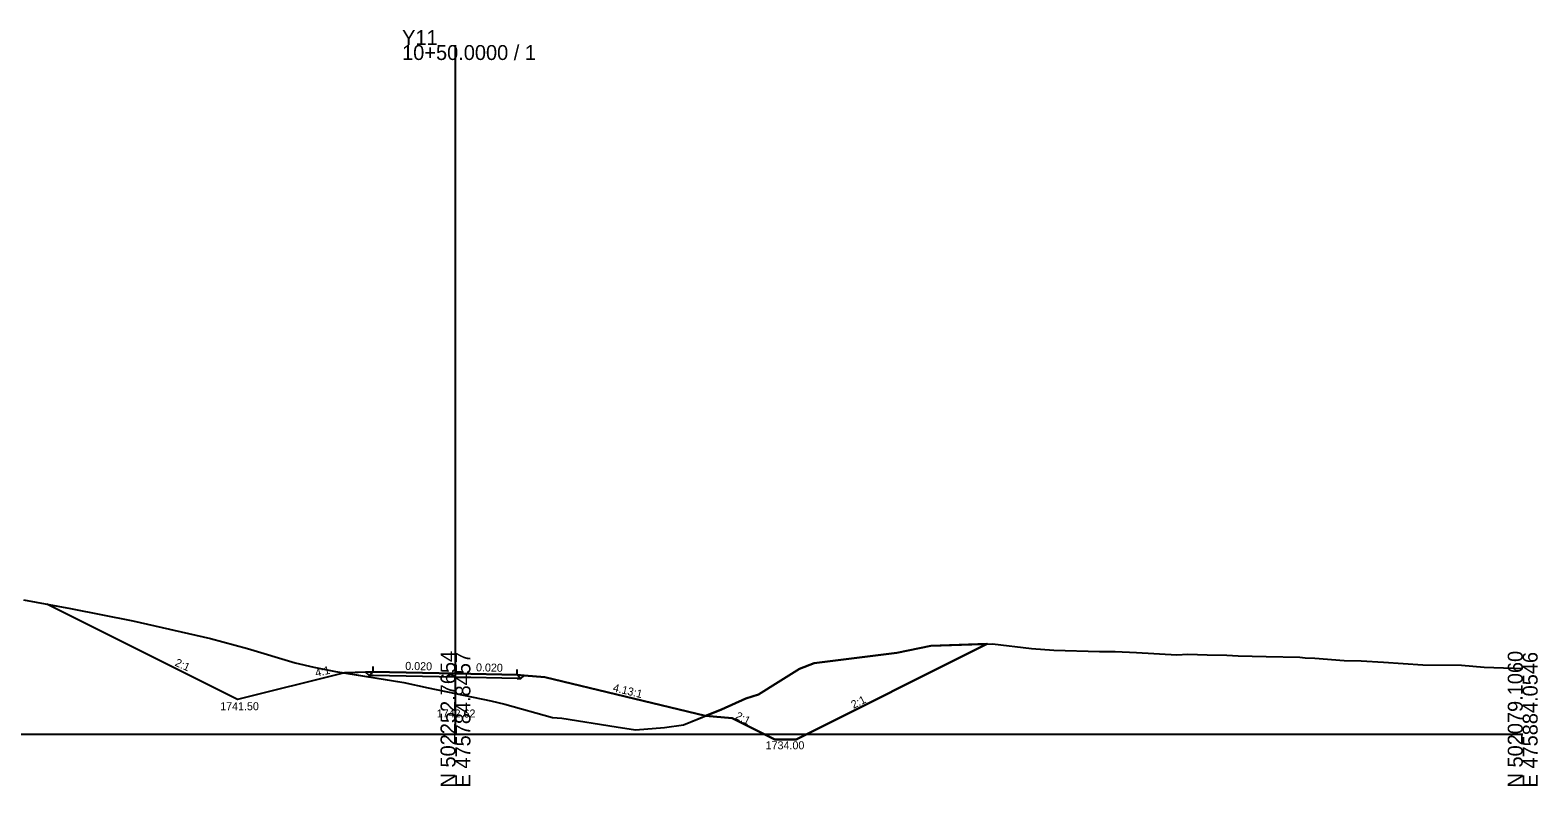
# Model space of a CAD drawing. Extents: x -76 to 353, y -10 to 8186.
# Drawn here: x 70.3 to 352.8, y 990.3 to 1132 of the extents above; entities that cross this region are included whole.
import ezdxf

# ---------------------------------------------------------------- set-up
doc = ezdxf.new("R2010")
doc.units = 0
for name, color, linetype in [('Exist Cross Section Cell', 7, 'Continuous'), ('Exist XS Center Line Elevation Label', 7, 'Continuous'), ('Exist XS Ground Line', 7, 'Continuous'), ('Prop XS DDE', 7, 'Continuous'), ('Prop XS DDE Earthwork Shape', 7, 'Continuous'), ('Prop XS Ditch Slope Text', 7, 'Continuous'), ('Prop XS Ditch Standard Text', 7, 'Continuous'), ('Prop XS Dump Level', 7, 'Continuous'), ('Prop XS Earthwork Shape', 7, 'Continuous'), ('Prop XS EOT Tick Mark', 7, 'Continuous'), ('Prop XS Finish Grade', 7, 'Continuous'), ('Prop XS Finish Grade Earthwork', 7, 'Continuous'), ('Prop XS Finish Grade Pavement', 7, 'Continuous'), ('Prop XS Hydro Fill Slope Data', 7, 'Continuous'), ('Prop XS Hydro Typical Ditch Data', 7, 'Continuous'), ('Prop XS Pvmt Edge Slope', 7, 'Continuous'), ('Prop XS SE Text', 7, 'Continuous'), ('Prop XS Shoulder Borrow Shape', 7, 'Continuous'), ('Prop XS Side Slope Text', 7, 'Continuous'), ('Prop XS Subgrade Earthwork', 7, 'Continuous'), ('Scratch_Level_3', 7, 'Continuous')]:
    doc.layers.add(name, color=color, linetype=linetype)

msp = doc.modelspace()

# ---------------------------------------------------------------- linework, layer by layer
at = {"layer": 'Exist Cross Section Cell'}
for p, q in [((150, 1000), (150, 1129.16)), ((-50, 1000), (150, 1000)), ((150, 1000), (350, 1000))]:
    msp.add_line(p, q, dxfattribs=at)
at = {"layer": 'Exist XS Ground Line'}
msp.add_lwpolyline([(69.06, 1025.17), (77.84, 1023.54), (89.53, 1021.21), (104.1, 1017.94), (111.04, 1016.05), (119.93, 1013.39), (123.43, 1012.56), (127.52, 1011.74), (140.3, 1009.65), (144.88, 1008.69), (150, 1007.62), (156.63, 1006.23), (159.24, 1005.62), (168.21, 1003.15), (169.96, 1002.97), (180.14, 1001.4), (183.72, 1000.78), (189.17, 1001.22), (192.71, 1001.75), (199.86, 1004.61), (204.39, 1006.7), (206.81, 1007.44), (210.45, 1009.73), (214.49, 1012.24), (217.21, 1013.3), (232.73, 1015.23), (239.1, 1016.54), (250.62, 1016.94), (257.92, 1016.05), (262.14, 1015.77), (270.7, 1015.51), (273.66, 1015.46), (277.61, 1015.3), (285.18, 1014.89), (287.25, 1014.96), (290.86, 1014.85), (294.58, 1014.8), (296.7, 1014.69), (301.91, 1014.53), (308.22, 1014.4), (309.24, 1014.33), (311.02, 1014.23), (316.57, 1013.83), (319.74, 1013.73), (323.9, 1013.48), (331.26, 1012.98), (338.56, 1012.94), (342.78, 1012.55), (350, 1012.3)], dxfattribs=at)
at = {"layer": 'Prop XS DDE'}
for p, q in [((249.66, 1016.9), (213.85, 999)), ((201.86, 1003), (196.86, 1003.41)), ((209.85, 999), (201.86, 1003)), ((209.85, 999), (213.85, 999))]:
    msp.add_line(p, q, dxfattribs=at)
at = {"layer": 'Prop XS DDE Earthwork Shape'}
for points in [[(249.66, 1016.9), (213.85, 999), (209.85, 999), (201.86, 1003), (196.86, 1003.41), (199.86, 1004.61), (204.39, 1006.7), (206.81, 1007.44), (210.45, 1009.73), (214.49, 1012.24), (217.21, 1013.3), (232.73, 1015.23), (239.1, 1016.54)], [(206.81, 1007.44), (210.45, 1009.73), (214.49, 1012.24), (217.21, 1013.3), (232.73, 1015.23), (239.1, 1016.54), (249.66, 1016.9), (213.85, 999), (209.85, 999), (201.86, 1003), (196.86, 1003.41), (199.86, 1004.61), (204.39, 1006.7)]]:
    msp.add_lwpolyline(points, close=True, dxfattribs=at)
at = {"layer": 'Prop XS Dump Level'}
for p, q in [((150, 1011.34), (134.57, 1011.65)), ((161.56, 1011.11), (150, 1011.34))]:
    msp.add_line(p, q, dxfattribs=at)
at = {"layer": 'Prop XS Earthwork Shape'}
for points in [[(128.96, 1011.45), (109.15, 1006.5), (73.44, 1024.36), (77.84, 1023.54), (89.53, 1021.21), (104.1, 1017.94), (111.04, 1016.05), (119.93, 1013.39), (123.43, 1012.56), (127.52, 1011.74), (129.22, 1011.46)], [(150, 1010.67), (134.57, 1010.97), (134.57, 1010.98), (133.83, 1011), (133.16, 1011.6), (129.22, 1011.46), (140.3, 1009.65), (144.88, 1008.69), (150, 1007.62), (156.63, 1006.23), (159.24, 1005.62), (168.21, 1003.15), (169.96, 1002.97), (180.14, 1001.4), (183.72, 1000.78), (189.17, 1001.22), (192.71, 1001.75), (196.86, 1003.41), (166.72, 1010.71), (162.86, 1011.01), (162.26, 1010.43), (161.56, 1010.44)]]:
    msp.add_lwpolyline(points, close=True, dxfattribs=at)
at = {"layer": 'Prop XS EOT Tick Mark'}
for p, q in [((134.57, 1011.65), (134.57, 1012.65)), ((161.56, 1011.11), (161.56, 1012.11))]:
    msp.add_line(p, q, dxfattribs=at)
at = {"layer": 'Prop XS Finish Grade'}
for p, q in [((134.57, 1011.65), (133.16, 1011.6)), ((161.56, 1011.11), (162.86, 1011.01))]:
    msp.add_line(p, q, dxfattribs=at)
at = {"layer": 'Prop XS Finish Grade Earthwork'}
for p, q in [((109.15, 1006.5), (73.44, 1024.36)), ((133.16, 1011.6), (128.96, 1011.45)), ((128.96, 1011.45), (109.15, 1006.5)), ((162.86, 1011.01), (166.72, 1010.71)), ((166.72, 1010.71), (196.86, 1003.41))]:
    msp.add_line(p, q, dxfattribs=at)
at = {"layer": 'Prop XS Finish Grade Pavement'}
for p, q in [((134.57, 1011.65), (150, 1011.34)), ((150, 1011.34), (161.56, 1011.11))]:
    msp.add_line(p, q, dxfattribs=at)
at = {"layer": 'Prop XS Hydro Fill Slope Data'}
msp.add_line((166.72, 1010.71), (196.86, 1003.41), dxfattribs=at)
at = {"layer": 'Prop XS Hydro Typical Ditch Data'}
for p, q in [((109.15, 1006.5), (73.44, 1024.36)), ((128.96, 1011.45), (109.15, 1006.5))]:
    msp.add_line(p, q, dxfattribs=at)
at = {"layer": 'Prop XS Pvmt Edge Slope'}
for p, q in [((134.57, 1011.65), (133.83, 1011)), ((161.56, 1011.11), (162.26, 1010.43))]:
    msp.add_line(p, q, dxfattribs=at)
at = {"layer": 'Prop XS Shoulder Borrow Shape'}
for points in [[(134.57, 1011.65), (133.83, 1011), (133.16, 1011.6)], [(134.57, 1011.65), (133.83, 1011), (133.16, 1011.6)], [(162.26, 1010.43), (162.86, 1011.01), (161.56, 1011.11)], [(162.26, 1010.43), (162.86, 1011.01), (161.56, 1011.11)]]:
    msp.add_lwpolyline(points, close=True, dxfattribs=at)
at = {"layer": 'Prop XS Subgrade Earthwork'}
for p, q in [((133.83, 1011), (133.16, 1011.6)), ((134.57, 1010.98), (133.83, 1011)), ((134.57, 1010.98), (134.57, 1010.97)), ((150, 1010.67), (134.57, 1010.97)), ((161.56, 1010.44), (150, 1010.67)), ((161.56, 1010.44), (162.26, 1010.43)), ((162.26, 1010.43), (162.86, 1011.01))]:
    msp.add_line(p, q, dxfattribs=at)
at = {"layer": 'Scratch_Level_3'}
for p, q in [((213.85, 999), (249.66, 1016.9)), ((249.66, 1016.9), (239.1, 1016.54)), ((196.86, 1003.41), (201.86, 1003)), ((201.86, 1003), (209.85, 999)), ((209.85, 999), (213.85, 999))]:
    msp.add_line(p, q, dxfattribs=at)
for points in [[(239.1, 1016.54), (232.73, 1015.23), (217.21, 1013.3), (214.49, 1012.24), (210.45, 1009.73), (206.81, 1007.44), (204.39, 1006.7), (199.86, 1004.61), (196.86, 1003.41)], [(196.86, 1003.41), (196.86, 1003.41)]]:
    msp.add_lwpolyline(points, dxfattribs=at)

# ---------------------------------------------------------------- texts
at = {"layer": 'Exist Cross Section Cell'}
for s, p in [('Y11', (140, 1129.16)), ('10+50.0000 / 1', (140, 1126.36))]:
    msp.add_text(s, height=2.8, dxfattribs=at).set_placement(p)
for s, p in [('N 502252.7654', (150, 990)), ('E 475784.8457', (152.8, 990)), ('N 502079.1060', (350, 990)), ('E 475884.0546', (352.8, 990))]:
    msp.add_text(s, height=2.8, rotation=90, dxfattribs=at).set_placement(p)
at = {"layer": 'Exist XS Center Line Elevation Label'}
msp.add_text('1742.62', height=1.5, dxfattribs=at).set_placement((146.49, 1003.12))
at = {"layer": 'Prop XS Ditch Slope Text'}
msp.add_text('4:1', height=1.5, rotation=12.5619, dxfattribs=at).set_placement((123.88, 1010.74))
at = {"layer": 'Prop XS Ditch Standard Text'}
for s, p in [('1741.50', (105.91, 1004.48)), ('1734.00', (208.13, 997.16))]:
    msp.add_text(s, height=1.5, dxfattribs=at).set_placement(p)
at = {"layer": 'Prop XS Dump Level'}
for p in [(128.96, 1011.41), (166.72, 1010.67)]:
    msp.add_text('Case1', height=0.04, dxfattribs=at).set_placement(p)
at = {"layer": 'Prop XS SE Text'}
for p in [(140.58, 1012.05), (153.84, 1011.78)]:
    msp.add_text('0.020', height=1.5, rotation=358.8542, dxfattribs=at).set_placement(p)
at = {"layer": 'Prop XS Side Slope Text'}
for s, rotation, p in [('2:1', 335.9796, (97.29, 1012.88)), ('4.13:1', 346.3858, (179.41, 1008.05)), ('2:1', 26.5651, (224.59, 1004.73)), ('2:1', 333.4349, (202.31, 1002.95))]:
    msp.add_text(s, height=1.5, rotation=rotation, dxfattribs=at).set_placement(p)

doc.saveas('drawing.dxf')
